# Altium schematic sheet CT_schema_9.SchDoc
size 287 x 160 mm
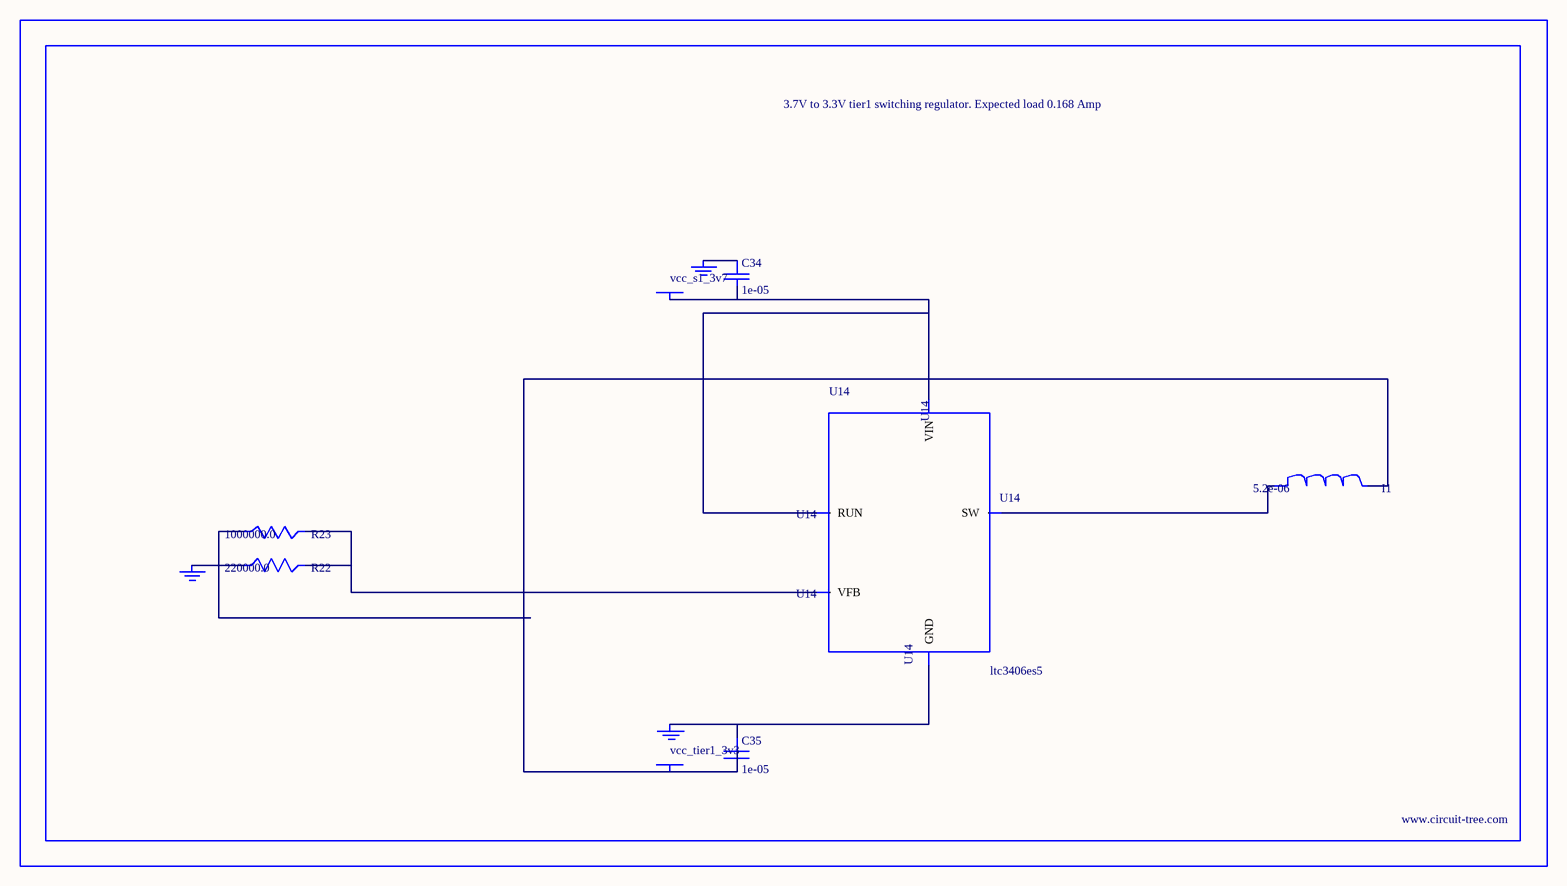
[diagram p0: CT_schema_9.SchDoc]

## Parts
BORDER8  (no value)
C34  1e-05  [C0805]
C35  1e-05  [C0805]
GND_INSTANCE_8_0  (no value)
GND_INSTANCE_8_1  (no value)
GND_INSTANCE_8_2  (no value)
I1  5.2e-06  [DR1040]
POWER_INSTANCE_8_0  vcc_tier1_3v3
POWER_INSTANCE_8_1  vcc_s1_3v7
R22  220000.0  [R0603]
R23  1000000.0  [R0603]
U14  ltc3406es5  [TSOT-23-5]

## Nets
NetC34_1: C34.1 GND_INSTANCE_8_1.0(GND)
NetC34_2: C34.2 POWER_INSTANCE_8_1.0(PWR) U14.1(RUN) U14.4(VIN)
NetC35_1: C35.1 GND_INSTANCE_8_0.0(GND) U14.2(GND)
NetC35_2: C35.2 I1.2 POWER_INSTANCE_8_0.0(PWR) R23.1
NetGND_INSTANCE_8_2_0: GND_INSTANCE_8_2.0(GND) R22.1
NetI1_1: I1.1 U14.3(SW)
NetR22_2: R22.2 R23.2 U14.5(VFB)

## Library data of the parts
BORDER8 = BORDER_PAGE8
C34 C35 = C0805C106K8RACTU
GND_INSTANCE_8_0-GND_INSTANCE_8_2 = GND
I1 = DR1040-5R2-R
POWER_INSTANCE_8_0 POWER_INSTANCE_8_1 = PWR
R22 = RC0603JR-07220KL
R23 = RC0603JR-071ML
